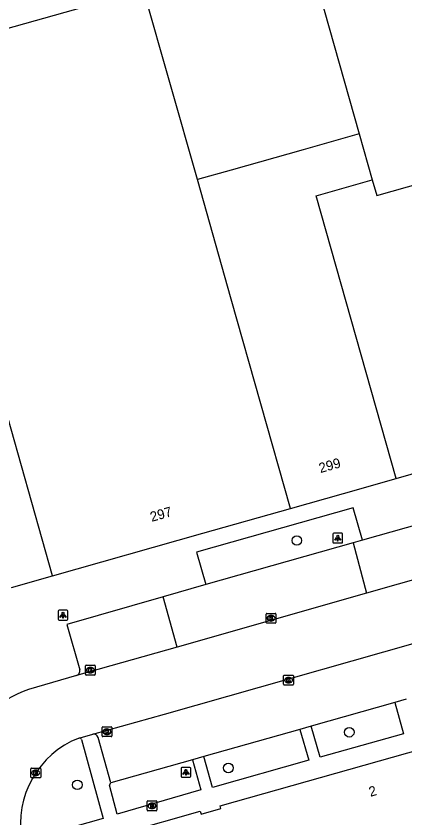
# Model space of a CAD drawing. Extents: x 159689 to 160786, y 387323 to 388339.
# Drawn here: x 159801.3 to 159840.8, y 388088.3 to 388169.7 of the extents above; entities that cross this region are included whole.
import ezdxf

# ---------------------------------------------------------------- set-up
doc = ezdxf.new("R2010")
doc.units = 0
for name, color, linetype in [('IMGEO_Boom', 7, 'Continuous'), ('IMGEO_Brandkraan', 7, 'Continuous'), ('IMGEO_Kolk', 7, 'Continuous'), ('IMGEO_Lichtpunt', 7, 'Continuous'), ('IMGEO_Pand', 7, 'Continuous'), ('IMGEO_Pand_nummerreeks', 7, 'Continuous'), ('IMGEO_Parkeervlak_open', 7, 'Continuous'), ('IMGEO_Rijbaan_lokaal_gesloten', 7, 'Continuous'), ('IMGEO_Voetpad_open', 7, 'Continuous')]:
    doc.layers.add(name, color=color, linetype=linetype)

msp = doc.modelspace()

# ---------------------------------------------------------------- linework, layer by layer
at = {"layer": 'IMGEO_Boom'}
for centre in [(159829.818, 388116.474), (159835.134, 388096.996), (159822.879, 388093.365), (159807.547, 388091.653)]:
    msp.add_circle(centre, 0.489, dxfattribs=at)
at = {"layer": 'IMGEO_Brandkraan'}
for p, q in [((159814.628, 388089.101), (159814.628, 388089.953)), ((159814.703, 388090.027), (159815.555, 388090.027)), ((159815.116, 388089.807), (159815.141, 388089.807)), ((159815.629, 388089.953), (159815.629, 388089.101)), ((159815.555, 388089.027), (159814.703, 388089.027)), ((159815.139, 388089.247), (159815.114, 388089.247))]:
    msp.add_line(p, q, dxfattribs=at)
for points in [[(159814.628, 388089.101), (159814.628, 388089.953)], [(159814.703, 388090.027), (159815.555, 388090.027)], [(159814.976, 388089.727), (159814.976, 388089.327), (159815.189, 388089.327)], [(159815.207, 388089.727), (159814.976, 388089.727)], [(159815.155, 388089.646), (159815.101, 388089.646), (159815.101, 388089.57)], [(159815.101, 388089.57), (159815.154, 388089.57)], [(159815.629, 388089.953), (159815.629, 388089.101)], [(159815.555, 388089.027), (159814.703, 388089.027)], [(159815.163, 388089.494), (159815.101, 388089.494), (159815.101, 388089.413)], [(159815.101, 388089.413), (159815.163, 388089.413)]]:
    msp.add_lwpolyline(points, dxfattribs=at)
for centre, radius, start, end in [((159814.705, 388089.951), 0.0765, 91.55205, 178.44795), ((159814.705, 388089.951), 0.0765, 91.55205, 178.44795), ((159815.156, 388089.608), 0.0379, 267.82845, 90.93552), ((159815.211, 388089.582), 0.145, 59.4692, 91.53667), ((159815.236, 388089.629), 0.0922, 285.51372, 58.15012), ((159815.553, 388089.951), 0.0765, 1.55205, 88.44795), ((159815.553, 388089.951), 0.0765, 1.55205, 88.44795), ((159814.705, 388089.103), 0.0765, 181.55205, 268.44795), ((159814.705, 388089.103), 0.0765, 181.55205, 268.44795), ((159815.164, 388089.453), 0.0404, 269.87594, 90.50774), ((159815.195, 388089.578), 0.251, 268.66757, 293.53466), ((159815.241, 388089.437), 0.105, 301.31148, 78.98903), ((159815.553, 388089.103), 0.0765, 271.55205, 358.44795), ((159815.553, 388089.103), 0.0765, 271.55205, 358.44795)]:
    msp.add_arc(centre, radius, start, end, dxfattribs=at)
for centre, major_axis, ratio, start_param, end_param in [((159815.115, 388089.527), (-0.387, 0.002), 0.722429, 4.712389, 7.853982), ((159815.14, 388089.527), (-0.39, 0.002), 0.717154, 1.570796, 4.712389)]:
    msp.add_ellipse(centre, major_axis=major_axis, ratio=ratio, start_param=start_param, end_param=end_param, dxfattribs=at)
at = {"layer": 'IMGEO_Kolk'}
for p, q in [((159826.701, 388108.147), (159826.701, 388108.999)), ((159826.776, 388109.073), (159827.628, 388109.073)), ((159827.189, 388108.853), (159827.214, 388108.853)), ((159827.702, 388108.999), (159827.702, 388108.147)), ((159827.628, 388108.073), (159826.776, 388108.073)), ((159827.212, 388108.293), (159827.187, 388108.293)), ((159808.365, 388102.881), (159808.365, 388103.733)), ((159808.44, 388103.807), (159809.292, 388103.807)), ((159808.853, 388103.587), (159808.878, 388103.587)), ((159809.366, 388103.733), (159809.366, 388102.881)), ((159809.292, 388102.807), (159808.44, 388102.807)), ((159808.876, 388103.027), (159808.851, 388103.027)), ((159828.474, 388101.862), (159828.474, 388102.714)), ((159828.549, 388102.788), (159829.401, 388102.788)), ((159829.475, 388102.714), (159829.475, 388101.862)), ((159829.401, 388101.788), (159828.549, 388101.788)), ((159828.985, 388102.008), (159828.96, 388102.008)), ((159828.962, 388102.568), (159828.987, 388102.568)), ((159810.057, 388096.623), (159810.057, 388097.475)), ((159810.132, 388097.549), (159810.984, 388097.549)), ((159810.545, 388097.329), (159810.57, 388097.329)), ((159811.058, 388097.475), (159811.058, 388096.623)), ((159810.984, 388096.549), (159810.132, 388096.549)), ((159810.568, 388096.769), (159810.543, 388096.769)), ((159802.834, 388092.435), (159802.834, 388093.287)), ((159802.909, 388093.361), (159803.761, 388093.361)), ((159803.322, 388093.141), (159803.347, 388093.141)), ((159803.835, 388093.287), (159803.835, 388092.435)), ((159803.761, 388092.361), (159802.909, 388092.361)), ((159803.345, 388092.581), (159803.32, 388092.581))]:
    msp.add_line(p, q, dxfattribs=at)
for points in [[(159826.701, 388108.147), (159826.701, 388108.999)], [(159826.776, 388109.073), (159827.628, 388109.073)], [(159827.022, 388108.773), (159827.145, 388108.773), (159827.145, 388108.622), (159827.275, 388108.773), (159827.439, 388108.773), (159827.293, 388108.622), (159827.446, 388108.373), (159827.294, 388108.373), (159827.209, 388108.537), (159827.145, 388108.47), (159827.145, 388108.373), (159827.022, 388108.373), (159827.022, 388108.773)], [(159827.702, 388108.999), (159827.702, 388108.147)], [(159827.628, 388108.073), (159826.776, 388108.073)], [(159808.365, 388102.881), (159808.365, 388103.733)], [(159808.44, 388103.807), (159809.292, 388103.807)], [(159808.686, 388103.507), (159808.809, 388103.507), (159808.809, 388103.356), (159808.939, 388103.507), (159809.103, 388103.507), (159808.957, 388103.356), (159809.11, 388103.107), (159808.958, 388103.107), (159808.873, 388103.271), (159808.809, 388103.204), (159808.809, 388103.107), (159808.686, 388103.107), (159808.686, 388103.507)], [(159809.366, 388103.733), (159809.366, 388102.881)], [(159809.292, 388102.807), (159808.44, 388102.807)], [(159828.474, 388101.862), (159828.474, 388102.714)], [(159828.549, 388102.788), (159829.401, 388102.788)], [(159829.475, 388102.714), (159829.475, 388101.862)], [(159829.401, 388101.788), (159828.549, 388101.788)], [(159828.795, 388102.488), (159828.918, 388102.488), (159828.918, 388102.337), (159829.048, 388102.488), (159829.212, 388102.488), (159829.066, 388102.337), (159829.219, 388102.088), (159829.067, 388102.088), (159828.982, 388102.252), (159828.918, 388102.185), (159828.918, 388102.088), (159828.795, 388102.088), (159828.795, 388102.488)], [(159810.057, 388096.623), (159810.057, 388097.475)], [(159810.132, 388097.549), (159810.984, 388097.549)], [(159810.378, 388097.249), (159810.501, 388097.249), (159810.501, 388097.098), (159810.631, 388097.249), (159810.795, 388097.249), (159810.649, 388097.098), (159810.802, 388096.849), (159810.65, 388096.849), (159810.565, 388097.013), (159810.501, 388096.946), (159810.501, 388096.849), (159810.378, 388096.849), (159810.378, 388097.249)], [(159811.058, 388097.475), (159811.058, 388096.623)], [(159810.984, 388096.549), (159810.132, 388096.549)], [(159802.834, 388092.435), (159802.834, 388093.287)], [(159802.909, 388093.361), (159803.761, 388093.361)], [(159803.155, 388093.061), (159803.278, 388093.061), (159803.278, 388092.91), (159803.408, 388093.061), (159803.572, 388093.061), (159803.426, 388092.91), (159803.579, 388092.661), (159803.427, 388092.661), (159803.342, 388092.825), (159803.278, 388092.758), (159803.278, 388092.661), (159803.155, 388092.661), (159803.155, 388093.061)], [(159803.835, 388093.287), (159803.835, 388092.435)], [(159803.761, 388092.361), (159802.909, 388092.361)]]:
    msp.add_lwpolyline(points, dxfattribs=at)
for centre, start, end in [((159826.778, 388108.997), 91.55205, 178.44795), ((159826.778, 388108.997), 91.55205, 178.44795), ((159827.626, 388108.997), 1.55205, 88.44795), ((159827.626, 388108.997), 1.55205, 88.44795), ((159826.778, 388108.149), 181.55205, 268.44795), ((159826.778, 388108.149), 181.55205, 268.44795), ((159827.626, 388108.149), 271.55205, 358.44795), ((159827.626, 388108.149), 271.55205, 358.44795), ((159808.442, 388103.731), 91.55205, 178.44795), ((159808.442, 388103.731), 91.55205, 178.44795), ((159809.29, 388103.731), 1.55205, 88.44795), ((159809.29, 388103.731), 1.55205, 88.44795), ((159808.442, 388102.883), 181.55205, 268.44795), ((159808.442, 388102.883), 181.55205, 268.44795), ((159809.29, 388102.883), 271.55205, 358.44795), ((159809.29, 388102.883), 271.55205, 358.44795), ((159828.551, 388102.712), 91.55205, 178.44795), ((159828.551, 388102.712), 91.55205, 178.44795), ((159829.399, 388102.712), 1.55205, 88.44795), ((159829.399, 388102.712), 1.55205, 88.44795), ((159828.551, 388101.864), 181.55205, 268.44795), ((159828.551, 388101.864), 181.55205, 268.44795), ((159829.399, 388101.864), 271.55205, 358.44795), ((159829.399, 388101.864), 271.55205, 358.44795), ((159810.134, 388097.473), 91.55205, 178.44795), ((159810.134, 388097.473), 91.55205, 178.44795), ((159810.982, 388097.473), 1.55205, 88.44795), ((159810.982, 388097.473), 1.55205, 88.44795), ((159810.134, 388096.625), 181.55205, 268.44795), ((159810.134, 388096.625), 181.55205, 268.44795), ((159810.982, 388096.625), 271.55205, 358.44795), ((159810.982, 388096.625), 271.55205, 358.44795), ((159802.911, 388093.285), 91.55205, 178.44795), ((159802.911, 388093.285), 91.55205, 178.44795), ((159803.759, 388093.285), 1.55205, 88.44795), ((159803.759, 388093.285), 1.55205, 88.44795), ((159802.911, 388092.437), 181.55205, 268.44795), ((159802.911, 388092.437), 181.55205, 268.44795), ((159803.759, 388092.437), 271.55205, 358.44795), ((159803.759, 388092.437), 271.55205, 358.44795)]:
    msp.add_arc(centre, 0.0765, start, end, dxfattribs=at)
for centre, major_axis, ratio, start_param, end_param in [((159827.188, 388108.573), (-0.387, 0.002), 0.722429, 4.712389, 7.853982), ((159827.213, 388108.573), (-0.39, 0.002), 0.717154, 1.570796, 4.712389), ((159808.852, 388103.307), (-0.387, 0.002), 0.722429, 4.712389, 7.853982), ((159808.877, 388103.307), (-0.39, 0.002), 0.717154, 1.570796, 4.712389), ((159828.961, 388102.288), (-0.387, 0.002), 0.722429, 4.712389, 7.853982), ((159828.986, 388102.288), (-0.39, 0.002), 0.717154, 1.570796, 4.712389), ((159810.544, 388097.049), (-0.387, 0.002), 0.722429, 4.712389, 7.853982), ((159810.569, 388097.049), (-0.39, 0.002), 0.717154, 1.570796, 4.712389), ((159803.321, 388092.861), (-0.387, 0.002), 0.722429, 4.712389, 7.853982), ((159803.346, 388092.861), (-0.39, 0.002), 0.717154, 1.570796, 4.712389)]:
    msp.add_ellipse(centre, major_axis=major_axis, ratio=ratio, start_param=start_param, end_param=end_param, dxfattribs=at)
at = {"layer": 'IMGEO_Lichtpunt'}
for p, q in [((159833.469, 388117.122), (159833.469, 388116.315)), ((159833.469, 388117.122), (159833.469, 388116.315)), ((159834.371, 388117.217), (159833.563, 388117.217)), ((159834.371, 388117.217), (159833.563, 388117.217)), ((159834.465, 388116.315), (159834.465, 388117.122)), ((159834.465, 388116.315), (159834.465, 388117.122)), ((159833.563, 388116.221), (159834.371, 388116.221)), ((159833.563, 388116.221), (159834.371, 388116.221)), ((159805.6, 388109.292), (159805.6, 388108.485)), ((159805.6, 388109.292), (159805.6, 388108.485)), ((159806.502, 388109.387), (159805.694, 388109.387)), ((159806.502, 388109.387), (159805.694, 388109.387)), ((159806.596, 388108.485), (159806.596, 388109.292)), ((159806.596, 388108.485), (159806.596, 388109.292)), ((159805.694, 388108.391), (159806.502, 388108.391)), ((159805.694, 388108.391), (159806.502, 388108.391)), ((159818.072, 388093.329), (159818.072, 388092.522)), ((159818.072, 388093.329), (159818.072, 388092.522)), ((159818.974, 388093.424), (159818.166, 388093.424)), ((159818.974, 388093.424), (159818.166, 388093.424)), ((159819.068, 388092.522), (159819.068, 388093.329)), ((159819.068, 388092.522), (159819.068, 388093.329)), ((159818.166, 388092.428), (159818.974, 388092.428)), ((159818.166, 388092.428), (159818.974, 388092.428))]:
    msp.add_line(p, q, dxfattribs=at)
for points in [[(159833.843, 388116.786), (159833.882, 388116.758), (159833.694, 388116.496), (159833.656, 388116.523), (159833.843, 388116.786)], [(159833.945, 388116.738), (159833.992, 388116.738), (159833.992, 388116.416), (159833.945, 388116.416), (159833.945, 388116.738)], [(159834.055, 388116.758), (159834.093, 388116.785), (159834.28, 388116.523), (159834.241, 388116.495), (159834.055, 388116.758)], [(159805.974, 388108.956), (159806.013, 388108.928), (159805.825, 388108.666), (159805.787, 388108.693), (159805.974, 388108.956)], [(159806.076, 388108.908), (159806.123, 388108.908), (159806.123, 388108.586), (159806.076, 388108.586), (159806.076, 388108.908)], [(159806.186, 388108.928), (159806.224, 388108.955), (159806.411, 388108.693), (159806.372, 388108.665), (159806.186, 388108.928)], [(159818.446, 388092.993), (159818.485, 388092.965), (159818.297, 388092.703), (159818.259, 388092.73), (159818.446, 388092.993)], [(159818.548, 388092.945), (159818.595, 388092.945), (159818.595, 388092.623), (159818.548, 388092.623), (159818.548, 388092.945)], [(159818.658, 388092.965), (159818.696, 388092.992), (159818.883, 388092.73), (159818.844, 388092.702), (159818.658, 388092.965)]]:
    msp.add_lwpolyline(points, dxfattribs=at)
for centre in [(159833.968, 388116.92), (159806.099, 388109.09), (159818.571, 388093.127)]:
    msp.add_circle(centre, 0.0994, dxfattribs=at)
for centre, start, end in [((159833.563, 388117.122), 90, 180), ((159833.563, 388117.122), 90, 180), ((159834.371, 388117.122), 0, 90), ((159834.371, 388117.122), 0, 90), ((159833.563, 388116.315), 180, 270), ((159833.563, 388116.315), 180, 270), ((159834.371, 388116.315), 270, 0), ((159834.371, 388116.315), 270, 360), ((159805.694, 388109.292), 90, 180), ((159805.694, 388109.292), 90, 180), ((159806.502, 388109.292), 0, 90), ((159806.502, 388109.292), 0, 90), ((159805.694, 388108.485), 180, 270), ((159805.694, 388108.485), 180, 270), ((159806.502, 388108.485), 270, 0), ((159806.502, 388108.485), 270, 360), ((159818.166, 388093.329), 90, 180), ((159818.166, 388093.329), 90, 180), ((159818.974, 388093.329), 0, 90), ((159818.974, 388093.329), 0, 90), ((159818.166, 388092.522), 180, 270), ((159818.166, 388092.522), 180, 270), ((159818.974, 388092.522), 270, 0), ((159818.974, 388092.522), 270, 360)]:
    msp.add_arc(centre, 0.0946, start, end, dxfattribs=at)
at = {"layer": 'IMGEO_Pand'}
for points in [[(159827.079, 388189.886), (159836.153, 388157.77)], [(159790.158, 388165.594), (159814.275, 388172.417)], [(159819.726, 388153.128), (159814.275, 388172.417)], [(159837.472, 388153.106), (159837.92, 388151.518), (159866.555, 388159.609)], [(159836.153, 388157.77), (159830.446, 388156.157), (159823.152, 388154.096), (159819.726, 388153.128)], [(159836.153, 388157.77), (159837.472, 388153.106)], [(159829.165, 388119.728), (159823.152, 388141.005), (159819.726, 388153.128)], [(159839.88, 388122.764), (159831.764, 388151.493), (159837.472, 388153.106)], [(159805.048, 388112.894), (159799.791, 388131.499), (159795.605, 388146.314), (159793.826, 388152.611)], [(159829.165, 388119.728), (159834.552, 388121.254), (159839.88, 388122.764)], [(159805.048, 388112.894), (159820.275, 388117.209), (159829.165, 388119.728)], [(159800.877, 388111.712), (159805.048, 388112.894)], [(159813.44, 388083.195), (159812.417, 388086.813), (159820.025, 388088.963), (159820.107, 388088.675), (159822.118, 388089.243), (159822.036, 388089.531), (159851.272, 388097.795), (159857.079, 388099.437), (159865.52, 388101.823)]]:
    msp.add_lwpolyline(points, dxfattribs=at)
at = {"layer": 'IMGEO_Parkeervlak_open'}
for points in [[(159835.533, 388116.227), (159820.599, 388111.991)], [(159839.764, 388100.021), (159831.272, 388097.596)], [(159830.131, 388097.27), (159820.371, 388094.523)], [(159819.222, 388094.198), (159810.943, 388091.858)]]:
    msp.add_lwpolyline(points, dxfattribs=at)
at = {"layer": 'IMGEO_Rijbaan_lokaal_gesloten'}
for points in [[(159846.773, 388113.929), (159836.895, 388111.119)], [(159836.895, 388111.119), (159817.68, 388105.652)], [(159809.123, 388096.793), (159816.406, 388098.822), (159848.286, 388107.894)], [(159817.68, 388105.652), (159807.454, 388102.743)], [(159807.454, 388102.743), (159802.605, 388101.325)], [(159807.72, 388096.406), (159809.038, 388096.769), (159809.123, 388096.793)]]:
    msp.add_lwpolyline(points, dxfattribs=at)
for centre, radius, start, end in [((159806.452, 388090.092), 11.873, 108.90437, 199.38793), ((159811.11, 388087.728), 9.316, 111.33818, 189.99653)]:
    msp.add_arc(centre, radius, start, end, dxfattribs=at)
at = {"layer": 'IMGEO_Voetpad_open'}
for points in [[(159839.88, 388122.764), (159845.753, 388124.456), (159856.524, 388127.56), (159862.486, 388129.241), (159874.181, 388132.474), (159871.844, 388140.895), (159871.595, 388141.772)], [(159836.471, 388116.493), (159835.536, 388119.807), (159819.649, 388115.289), (159820.599, 388111.991)], [(159845.338, 388119.014), (159836.471, 388116.493)], [(159836.471, 388116.493), (159835.533, 388116.227)], [(159835.533, 388116.227), (159836.895, 388111.119)], [(159820.599, 388111.991), (159816.252, 388110.741)], [(159816.252, 388110.741), (159806.486, 388107.932), (159807.797, 388103.336)], [(159817.68, 388105.652), (159816.252, 388110.741)], [(159840.921, 388100.351), (159839.764, 388100.021)], [(159839.764, 388100.021), (159840.648, 388096.841), (159832.2, 388094.465), (159831.272, 388097.596)], [(159830.131, 388097.27), (159831.022, 388094.146), (159821.251, 388091.397), (159820.371, 388094.523)], [(159831.272, 388097.596), (159830.131, 388097.27)], [(159807.964, 388096.274), (159810.181, 388088.241), (159802.17, 388085.979)], [(159810.943, 388091.858), (159809.657, 388096.473)], [(159820.371, 388094.523), (159819.222, 388094.198)], [(159819.222, 388094.198), (159820.067, 388091.135), (159811.592, 388088.673), (159810.823, 388091.626), (159810.943, 388091.858)]]:
    msp.add_lwpolyline(points, dxfattribs=at)
for centre, radius, start, end in [((159807.273, 388103.244), 0.532, 289.90161, 10.00694), ((159807.768, 388096.202), 0.209, 20.03096, 103.14372), ((159809.206, 388096.326), 0.474, 18.01035, 100.12527)]:
    msp.add_arc(centre, radius, start, end, dxfattribs=at)

# ---------------------------------------------------------------- texts
at = {"layer": 'IMGEO_Pand_nummerreeks'}
for s, rotation, p in [('299', 15.84222, (159832.209, 388123.316)), ('297', 15.82106, (159815.096, 388118.361)), ('2', 15.78375, (159837.279, 388090.431))]:
    msp.add_text(s, height=1, rotation=rotation, dxfattribs=at).set_placement(p)

doc.saveas('drawing.dxf')
